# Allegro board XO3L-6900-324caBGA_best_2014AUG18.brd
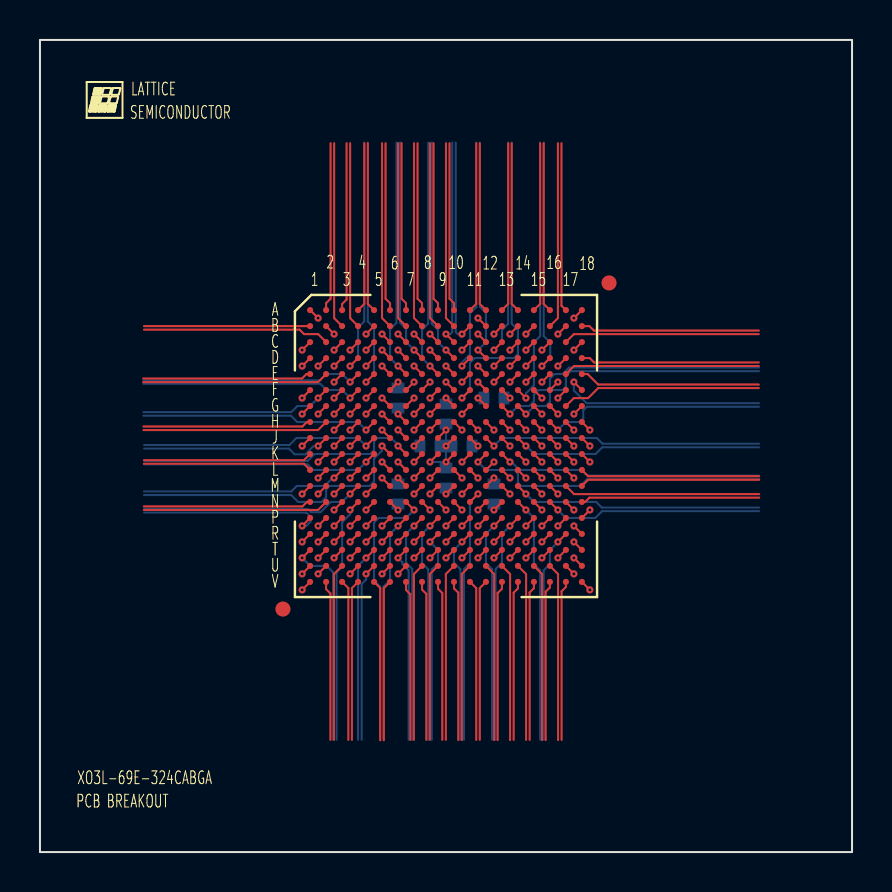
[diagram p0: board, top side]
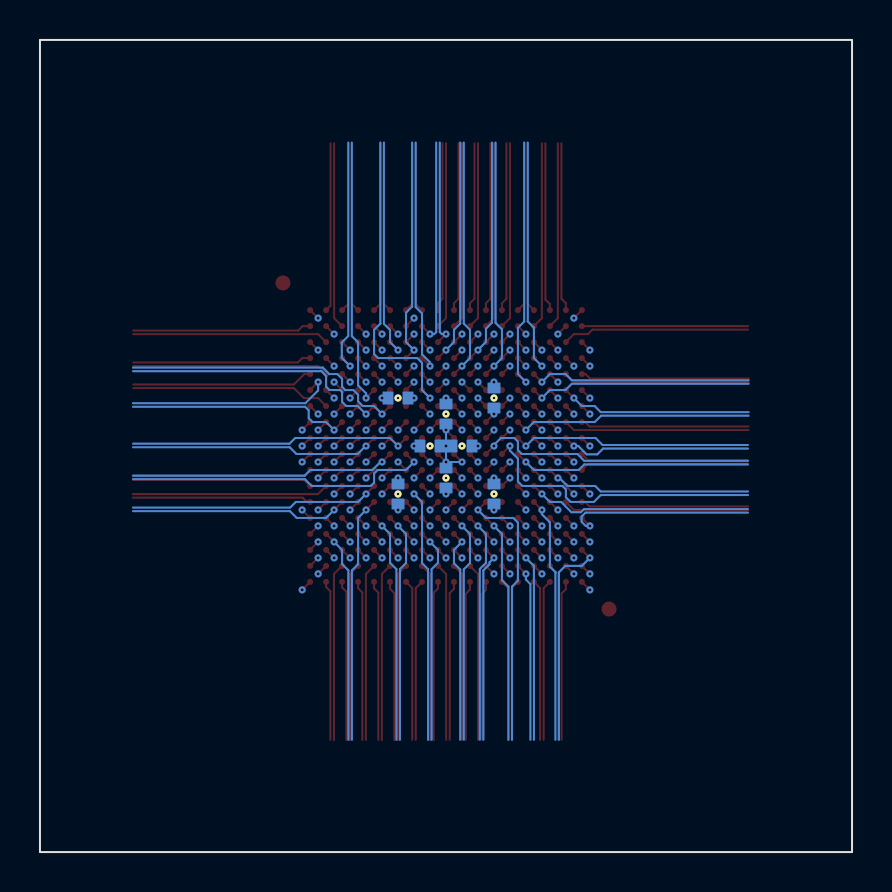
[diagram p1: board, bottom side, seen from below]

Outline 40.64 x 40.64 mm; copper layers: TOP, L2_GND, L3_SIGNAL, L4_SIGNAL, L5_PWR, BOTTOM. Coordinates in mm from the lower left corner of the outline.
Outline path: rectangle 0,0 40.64,40.64

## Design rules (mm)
net group CDPB4: nets PB4C PB4D
net group CDPB6: nets PB6C PB6D
net group CDPB7: nets PB7C PB7D
net group CDPB9: nets PB9C PB9D
net group CDPB13: nets PB13C PB13D
net group CDPB15: nets PB15C PB15D
net group CDPB16: nets PB16C PB16D
net group CDPB18: nets PB18C PB18D
net group CDPB21: nets PB21C PB21D
net group CDPB23: nets PB23C PB23D
net group CDPB26: nets PB26C PB26D
net group CDPB31: nets PB31C PB31D
net group CDPB35: nets PB35C PB35D
net group CDPB37: nets PB37C PB37D
net group CDPB38: nets PB38C PB38D
net group CDPL2: nets PL2C PL2D
net group CDPL3: nets PL3C PL3D
net group CDPL4: nets PL4C PL4D
net group CDPL5: nets PL5C PL5D
net group CDPL6: nets PL6C PL6D
net group CDPL7: nets PL7C PL7D
net group CDPL9: nets PL9C PL9D
net group CDPL10: nets PL10C PL10D
net group CDPL15: nets PL15C PL15D
net group CDPL16: nets PL16C PL16D
net group CDPL18: nets PL18C PL18D
net group CDPL19: nets PL19C PL19D
net group CDPL21: nets PL21C PL21D
net group CDPL23: nets PL23C PL23D
net group CDPL24: nets PL24C PL24D
net group CDPL25: nets PL25C PL25D
net group CDPR2: nets PR2C PR2D
net group CDPR3: nets PR3C PR3D
net group CDPR4: nets PR4C PR4D
net group CDPR6: nets PR6C PR6D
net group CDPR7: nets PR7C PR7D
net group CDPR8: nets PR8C PR8D
net group CDPR10: nets PR10C PR10D
net group CDPR11: nets PR11C PR11D
net group CDPR16: nets PR16C PR16D
net group CDPR17: nets PR17C PR17D
net group CDPR19: nets PR19C PR19D
net group CDPR21: nets PR21C PR21D
net group CDPR22: nets PR22C PR22D
net group CDPR23: nets PR23C PR23D
net group CDPR24: nets PR24C PR24D
net group CDPR25: nets PR25C PR25D
net group CDPT9: nets PT9C PT9D
net group CDPT10: nets PT10C PT10D
net group CDPT11: nets PT11C PT11D
net group CDPT14: nets PT14C PT14D
net group CDPT17: nets PT17C PT17D
net group CDPT18: nets PT18C PT18D
net group CDPT21: nets PT21C PT21D
net group CDPT22: nets PT22C PT22D
net group CDPT25: nets PT25C PT25D
net group CDPT26: nets PT26C PT26D
net group CDPT27: nets PT27C PT27D
net group CDPT33: nets PT33C PT33D
net group CDPT34: nets PT34C PT34D
net group CDPT35: nets PT35C PT35D
net group CDPT36: nets PT36C PT36D
net group PB4: nets PB4A PB4B
net group PB6: nets PB6A PB6B
net group PB7: nets PB7A PB7B
net group PB9: nets PB9A PB9B
net group PB10: nets PB10A PB10B
net group PB12: nets PB12A PB12B
net group PB13: nets PB13A PB13B
net group PB15: nets PB15A PB15B
net group PB16: nets PB16A PB16B
net group PB18: nets PB18A PB18B
net group PB21: nets PB21A PB21B
net group PB23: nets PB23A PB23B
net group PB26: nets PB26A PB26B
net group PB28: nets PB28A PB28B
net group PB29: nets PB29A PB29B
net group PB31: nets PB31A PB31B
net group PB32: nets PB32A PB32B
net group PB34: nets PB34A PB34B
net group PB35: nets PB35A PB35B
net group PB37: nets PB37A PB37B
net group PB38: nets PB38A PB38B
net group PL2: nets PL2A PL2B
net group PL3: nets PL3A PL3B
net group PL4: nets PL4A PL4B
net group PL5: nets PL5A PL5B
net group PL6: nets PL6A PL6B
net group PL8: nets PL8A PL8B
net group PL9: nets PL9A PL9B
net group PL10: nets PL10A PL10B
net group PL11: nets PL11A PL11B
net group PL12: nets PL12A PL12B
net group PL15: nets PL15A PL15B
net group PL17: nets PL17A PL17B
net group PL18: nets PL18A PL18B
net group PL19: nets PL19A PL19B
net group PL22: nets PL22A PL22B
net group PL23: nets PL23A PL23B
net group PL24: nets PL24A PL24B
net group PL25: nets PL25A PL25B
net group PR2: nets PR2A PR2B
net group PR3: nets PR3A PR3B
net group PR4: nets PR4A PR4B
net group PR5: nets PR5A PR5B
net group PR7: nets PR7A PR7B
net group PR8: nets PR8A PR8B
net group PR9: nets PR9A PR9B
net group PR11: nets PR11A PR11B
net group PR12: nets PR12A PR12B
net group PR15: nets PR15A PR15B
net group PR16: nets PR16A PR16B
net group PR17: nets PR17A PR17B
net group PR18: nets PR18A PR18B
net group PR21: nets PR21A PR21B
net group PR22: nets PR22A PR22B
net group PR23: nets PR23A PR23B
net group PR24: nets PR24A PR24B
net group PR25: nets PR25A PR25B
net group PT9: nets PT9A PT9B
net group PT10: nets PT10A PT10B
net group PT11: nets PT11A PT11B
net group PT12: nets PT12A PT12B
net group PT13: nets PT13A PT13B
net group PT14: nets PT14A PT14B
net group PT15: nets PT15A PT15B
net group PT16: nets PT16A PT16B
net group PT17: nets PT17A PT17B
net group PT18: nets PT18A PT18B
net group PT21: nets PT21A PT21B
net group PT22: nets PT22A PT22B
net group PT25: nets PT25A PT25B
net group PT26: nets PT26A PT26B
net group PT27: nets PT27A PT27B
net group PT28: nets PT28A PT28B
net group PT32: nets PT32A PT32B
net group PT33: nets PT33A PT33B
net group PT34: nets PT34A PT34B
net group PT35: nets PT35A PT35B
net group PT36: nets PT36A PT36B

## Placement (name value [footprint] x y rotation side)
BGA  -  [BGA324C80P18X18_1500X1500X17-1]  20.32 20.32 270 top
C1  VAL  [C0402]  17.92 22.72 90 bottom
C2  VAL  [C0402]  20.32 21.92 270 bottom
C3  VAL  [C0402]  22.72 17.92 270 bottom
C4  VAL  [C0402]  22.72 22.72 0 bottom
C5  VAL  [C0402]  19.52 20.32 0 bottom
C6  VAL  [C0402]  21.12 20.32 180 bottom
C7  VAL  [C0402]  20.32 18.72 90 bottom
C8  VAL  [C0402]  17.92 17.92 270 bottom
NOREF  -  []  24.69 13 0 top

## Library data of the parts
BGA = BGA324C80P18X18_1500X1500X17-1
C1-C8 = C0402: User Part Number: UPN; Tolerance: TOL

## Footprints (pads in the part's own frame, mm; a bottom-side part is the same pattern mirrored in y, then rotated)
BGA324C80P18X18_1500X1500X17-1
  round 0.75 smd: (-8.16,8.16) (8.16,-8.16)
  round 0.305 smd: A1(-6.8,-6.8) A2(-6.8,-6) A3(-6.8,-5.2) A4(-6.8,-4.4) A5(-6.8,-3.6) A6(-6.8,-2.8) A7(-6.8,-2) A8(-6.8,-1.2) A9(-6.8,-0.4) A10(-6.8,0.4) A11(-6.8,1.2) A12(-6.8,2) A13(-6.8,2.8) A14(-6.8,3.6) A15(-6.8,4.4) A16(-6.8,5.2) A17(-6.8,6) A18(-6.8,6.8) B1(-6,-6.8) B2(-6,-6) B3(-6,-5.2) B4(-6,-4.4) B5(-6,-3.6) B6(-6,-2.8) B7(-6,-2) B8(-6,-1.2) B9(-6,-0.4) B10(-6,0.4) B11(-6,1.2) B12(-6,2) B13(-6,2.8) B14(-6,3.6) B15(-6,4.4) B16(-6,5.2) B17(-6,6) B18(-6,6.8) C1(-5.2,-6.8) C2(-5.2,-6) C3(-5.2,-5.2) C4(-5.2,-4.4) C5(-5.2,-3.6) C6(-5.2,-2.8) C7(-5.2,-2) C8(-5.2,-1.2) C9(-5.2,-0.4) C10(-5.2,0.4) C11(-5.2,1.2) C12(-5.2,2) C13(-5.2,2.8) C14(-5.2,3.6) C15(-5.2,4.4) C16(-5.2,5.2) C17(-5.2,6) C18(-5.2,6.8) D1(-4.4,-6.8) D2(-4.4,-6) D3(-4.4,-5.2) D4(-4.4,-4.4) D5(-4.4,-3.6) D6(-4.4,-2.8) D7(-4.4,-2) D8(-4.4,-1.2) D9(-4.4,-0.4) D10(-4.4,0.4) D11(-4.4,1.2) D12(-4.4,2) D13(-4.4,2.8) D14(-4.4,3.6) D15(-4.4,4.4) D16(-4.4,5.2) D17(-4.4,6) D18(-4.4,6.8) E1(-3.6,-6.8) E2(-3.6,-6) E3(-3.6,-5.2) E4(-3.6,-4.4) E5(-3.6,-3.6) E6(-3.6,-2.8) E7(-3.6,-2) E8(-3.6,-1.2) E9(-3.6,-0.4) E10(-3.6,0.4) E11(-3.6,1.2) E12(-3.6,2) E13(-3.6,2.8) E14(-3.6,3.6) E15(-3.6,4.4) E16(-3.6,5.2) E17(-3.6,6) E18(-3.6,6.8) F1(-2.8,-6.8) F2(-2.8,-6) F3(-2.8,-5.2) F4(-2.8,-4.4) F5(-2.8,-3.6) F6(-2.8,-2.8) F7(-2.8,-2) F8(-2.8,-1.2) F9(-2.8,-0.4) F10(-2.8,0.4) F11(-2.8,1.2) F12(-2.8,2) F13(-2.8,2.8) F14(-2.8,3.6) F15(-2.8,4.4) F16(-2.8,5.2) F17(-2.8,6) F18(-2.8,6.8) G1(-2,-6.8) G2(-2,-6) G3(-2,-5.2) G4(-2,-4.4) G5(-2,-3.6) G6(-2,-2.8) G7(-2,-2) G8(-2,-1.2) G9(-2,-0.4) G10(-2,0.4) G11(-2,1.2) G12(-2,2) G13(-2,2.8) G14(-2,3.6) G15(-2,4.4) G16(-2,5.2) G17(-2,6) G18(-2,6.8) H1(-1.2,-6.8) H2(-1.2,-6) H3(-1.2,-5.2) H4(-1.2,-4.4) H5(-1.2,-3.6) H6(-1.2,-2.8) H7(-1.2,-2) H8(-1.2,-1.2) H9(-1.2,-0.4) H10(-1.2,0.4) H11(-1.2,1.2) H12(-1.2,2) H13(-1.2,2.8) H14(-1.2,3.6) H15(-1.2,4.4) H16(-1.2,5.2) H17(-1.2,6) H18(-1.2,6.8) J1(-0.4,-6.8) J2(-0.4,-6) J3(-0.4,-5.2) J4(-0.4,-4.4) J5(-0.4,-3.6) J6(-0.4,-2.8) J7(-0.4,-2) J8(-0.4,-1.2) J9(-0.4,-0.4) J10(-0.4,0.4) J11(-0.4,1.2) J12(-0.4,2) J13(-0.4,2.8) J14(-0.4,3.6) J15(-0.4,4.4) J16(-0.4,5.2) J17(-0.4,6) J18(-0.4,6.8) K1(0.4,-6.8) K2(0.4,-6) K3(0.4,-5.2) K4(0.4,-4.4) K5(0.4,-3.6) K6(0.4,-2.8) K7(0.4,-2) K8(0.4,-1.2) K9(0.4,-0.4) K10(0.4,0.4) K11(0.4,1.2) K12(0.4,2) K13(0.4,2.8) K14(0.4,3.6) K15(0.4,4.4) K16(0.4,5.2) K17(0.4,6) K18(0.4,6.8) L1(1.2,-6.8) L2(1.2,-6) L3(1.2,-5.2) L4(1.2,-4.4) L5(1.2,-3.6) L6(1.2,-2.8) L7(1.2,-2) L8(1.2,-1.2) L9(1.2,-0.4) L10(1.2,0.4) L11(1.2,1.2) L12(1.2,2) L13(1.2,2.8) L14(1.2,3.6) L15(1.2,4.4) L16(1.2,5.2) L17(1.2,6) L18(1.2,6.8) M1(2,-6.8) M2(2,-6) M3(2,-5.2) M4(2,-4.4) M5(2,-3.6) M6(2,-2.8) M7(2,-2) M8(2,-1.2) M9(2,-0.4) M10(2,0.4) M11(2,1.2) M12(2,2) M13(2,2.8) M14(2,3.6) M15(2,4.4) M16(2,5.2) M17(2,6) M18(2,6.8) N1(2.8,-6.8) N2(2.8,-6) N3(2.8,-5.2) N4(2.8,-4.4) N5(2.8,-3.6) N6(2.8,-2.8) N7(2.8,-2) N8(2.8,-1.2) N9(2.8,-0.4) N10(2.8,0.4) N11(2.8,1.2) N12(2.8,2) N13(2.8,2.8) N14(2.8,3.6) N15(2.8,4.4) N16(2.8,5.2) N17(2.8,6) N18(2.8,6.8) P1(3.6,-6.8) P2(3.6,-6) P3(3.6,-5.2) P4(3.6,-4.4) P5(3.6,-3.6) P6(3.6,-2.8) P7(3.6,-2) P8(3.6,-1.2) P9(3.6,-0.4) P10(3.6,0.4) P11(3.6,1.2) P12(3.6,2) P13(3.6,2.8) P14(3.6,3.6) P15(3.6,4.4) P16(3.6,5.2) P17(3.6,6) P18(3.6,6.8) R1(4.4,-6.8) R2(4.4,-6) R3(4.4,-5.2) R4(4.4,-4.4) R5(4.4,-3.6) R6(4.4,-2.8) R7(4.4,-2) R8(4.4,-1.2) R9(4.4,-0.4) R10(4.4,0.4) R11(4.4,1.2) R12(4.4,2) R13(4.4,2.8) R14(4.4,3.6) R15(4.4,4.4) R16(4.4,5.2) R17(4.4,6) R18(4.4,6.8) T1(5.2,-6.8) T2(5.2,-6) T3(5.2,-5.2) T4(5.2,-4.4) T5(5.2,-3.6) T6(5.2,-2.8) T7(5.2,-2) T8(5.2,-1.2) T9(5.2,-0.4) T10(5.2,0.4) T11(5.2,1.2) T12(5.2,2) T13(5.2,2.8) T14(5.2,3.6) T15(5.2,4.4) T16(5.2,5.2) T17(5.2,6) T18(5.2,6.8) U1(6,-6.8) U2(6,-6) U3(6,-5.2) U4(6,-4.4) U5(6,-3.6) U6(6,-2.8) U7(6,-2) U8(6,-1.2) U9(6,-0.4) U10(6,0.4) U11(6,1.2) U12(6,2) U13(6,2.8) U14(6,3.6) U15(6,4.4) U16(6,5.2) U17(6,6) U18(6,6.8) V1(6.8,-6.8) V2(6.8,-6) V3(6.8,-5.2) V4(6.8,-4.4) V5(6.8,-3.6) V6(6.8,-2.8) V7(6.8,-2) V8(6.8,-1.2) V9(6.8,-0.4) V10(6.8,0.4) V11(6.8,1.2) V12(6.8,2) V13(6.8,2.8) V14(6.8,3.6) V15(6.8,4.4) V16(6.8,5.2) V17(6.8,6) V18(6.8,6.8)
C0402
  rect 0.54x0.64 smd: 1(-0.5,0) 2(0.5,0)

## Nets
GND: BGA.A1 BGA.A18 BGA.B2 BGA.B17 BGA.F6 BGA.F13 BGA.J9 BGA.J10 BGA.K9 BGA.K10 BGA.N6 BGA.N13 BGA.U2 BGA.U17 BGA.V1 BGA.V18 C1.2 C2.2 C3.2 C4.2 C5.2 C6.2 C7.2 C8.2
VCC: BGA.G12 BGA.H8 BGA.H9 BGA.H10 BGA.H11 BGA.L8 BGA.L9 BGA.L10 BGA.L11 BGA.M12 C3.1 C4.1
VCCIO0: BGA.G8 BGA.G9 BGA.G10 BGA.G11 C2.1
VCCIO1: BGA.H12 BGA.J11 BGA.K11 BGA.L12 C6.1
VCCIO2: BGA.M8 BGA.M9 BGA.M10 BGA.M11 C7.1
VCCIO3: BGA.L7 BGA.M7 C8.1
VCCIO4: BGA.J8 BGA.K8 C5.1
VCCIO5: BGA.G7 BGA.H7 C1.1
PB4A: BGA.V2
PB4B: BGA.U3
PB4C: BGA.R4
PB4D: BGA.P6
PB6A: BGA.T3
PB6B: BGA.U4
PB6C: BGA.P5
PB6D: BGA.R6
PB7A: BGA.V3
PB7B: BGA.V4
PB7C: BGA.R5
PB7D: BGA.T4
PB9A: BGA.T5
PB9B: BGA.U5
PB9C: BGA.N7
PB9D: BGA.P7
PB10A: BGA.N8
PB10B: BGA.R7
PB12A: BGA.T6
PB12B: BGA.U6
PB13A: BGA.V5
PB13B: BGA.V6
PB13C: BGA.T7
PB13D: BGA.P8
PB15A: BGA.V7
PB15B: BGA.U8
PB15C: BGA.U7
PB15D: BGA.R8
PB16A: BGA.T8
PB16B: BGA.T9
PB16C: BGA.R9
PB16D: BGA.P9
PB18A: BGA.V8
PB18B: BGA.U9
PB18C: BGA.N9
PB18D: BGA.N10
PB21A: BGA.V9
PB21B: BGA.U10
PB21C: BGA.T10
PB21D: BGA.R10
PB23A: BGA.V10
PB23B: BGA.U11
PB23C: BGA.P10
PB23D: BGA.T11
PB26A: BGA.V11
PB26B: BGA.V12
PB26C: BGA.N11
PB26D: BGA.R11
PB28A: BGA.P11
PB28B: BGA.T12
PB29A: BGA.U12
PB29B: BGA.V13
PB31A: BGA.U13
PB31B: BGA.V14
PB31C: BGA.R12
PB31D: BGA.T13
PB32A: BGA.T14
PB32B: BGA.N12
PB34A: BGA.U14
PB34B: BGA.V15
PB35A: BGA.U15
PB35B: BGA.V16
PB35C: BGA.P12
PB35D: BGA.R14
PB37A: BGA.T15
PB37B: BGA.T16
PB37C: BGA.R13
PB37D: BGA.R15
PB38A: BGA.U16
PB38B: BGA.V17
PB38C: BGA.P13
PB38D: BGA.P14
PL2A: BGA.B1
PL2B: BGA.C2
PL2C: BGA.D3
PL2D: BGA.C1
PL3A: BGA.E4
PL3B: BGA.F4
PL3C: BGA.E3
PL3D: BGA.F5
PL4A: BGA.D2
PL4B: BGA.G5
PL4C: BGA.F3
PL4D: BGA.D1
PL5A: BGA.E2
PL5B: BGA.E1
PL5C: BGA.F2
PL5D: BGA.H5
PL6A: BGA.G4
PL6B: BGA.G3
PL6C: BGA.F1
PL6D: BGA.G6
PL7C: BGA.H3
PL7D: BGA.H4
PL8A: BGA.G2
PL8B: BGA.G1
PL9A: BGA.H2
PL9B: BGA.H1
PL9C: BGA.H6
PL9D: BGA.J1
PL10A: BGA.J2
PL10B: BGA.J5
PL10C: BGA.J3
PL10D: BGA.J7
PL11A: BGA.J4
PL11B: BGA.K3
PL12A: BGA.K2
PL12B: BGA.J6
PL15A: BGA.K1
PL15B: BGA.L1
PL15C: BGA.K7
PL15D: BGA.K5
PL16C: BGA.K6
PL16D: BGA.L3
PL17A: BGA.K4
PL17B: BGA.L2
PL18A: BGA.L4
PL18B: BGA.M2
PL18C: BGA.M1
PL18D: BGA.L6
PL19A: BGA.N1
PL19B: BGA.N2
PL19C: BGA.M3
PL19D: BGA.L5
PL21C: BGA.M5
PL21D: BGA.N3
PL22A: BGA.P1
PL22B: BGA.M4
PL23A: BGA.R1
PL23B: BGA.P3
PL23C: BGA.P2
PL23D: BGA.M6
PL24A: BGA.N4
PL24B: BGA.T1
PL24C: BGA.R2
PL24D: BGA.U1
PL25A: BGA.T2
PL25B: BGA.N5
PL25C: BGA.P4
PL25D: BGA.R3
PR2A: BGA.B18
PR2B: BGA.C17
PR2C: BGA.F14
PR2D: BGA.D16
PR3A: BGA.E15
PR3B: BGA.C18
PR3C: BGA.G13
PR3D: BGA.G14
PR4A: BGA.F15
PR4B: BGA.D17
PR4C: BGA.E16
PR4D: BGA.H13
PR5A: BGA.G15
PR5B: BGA.F16
PR6C: BGA.E17
PR6D: BGA.D18
PR7A: BGA.G16
PR7B: BGA.H15
PR7C: BGA.H14
PR7D: BGA.F17
PR8A: BGA.E18
PR8B: BGA.G17
PR8C: BGA.H16
PR8D: BGA.F18
PR9A: BGA.J15
PR9B: BGA.H17
PR10C: BGA.J13
PR10D: BGA.G18
PR11A: BGA.J16
PR11B: BGA.J17
PR11C: BGA.J14
PR11D: BGA.J12
PR12A: BGA.H18
PR12B: BGA.K15
PR15A: BGA.K14
PR15B: BGA.J18
PR16A: BGA.K16
PR16B: BGA.K17
PR16C: BGA.K12
PR16D: BGA.K13
PR17A: BGA.K18
PR17B: BGA.L16
PR17C: BGA.L15
PR17D: BGA.L13
PR18A: BGA.L17
PR18B: BGA.M16
PR19C: BGA.L18
PR19D: BGA.M18
PR21A: BGA.M17
PR21B: BGA.N18
PR21C: BGA.L14
PR21D: BGA.N17
PR22A: BGA.M15
PR22B: BGA.P18
PR22C: BGA.M14
PR22D: BGA.N16
PR23A: BGA.P17
PR23B: BGA.N15
PR23C: BGA.R18
PR23D: BGA.M13
PR24A: BGA.P16
PR24B: BGA.T18
PR24C: BGA.R17
PR24D: BGA.N14
PR25A: BGA.P15
PR25B: BGA.U18
PR25C: BGA.R16
PR25D: BGA.T17
PT9A: BGA.A2
PT9B: BGA.B3
PT9C: BGA.D4
PT9D: BGA.E5
PT10A: BGA.C3
PT10B: BGA.C4
PT10C: BGA.F7
PT10D: BGA.E6
PT11A: BGA.A3
PT11B: BGA.B4
PT11C: BGA.D5
PT11D: BGA.B5
PT12A: BGA.A4
PT12B: BGA.A5
PT13A: BGA.C5
PT13B: BGA.D6
PT14A: BGA.B6
PT14B: BGA.A6
PT14C: BGA.D7
PT14D: BGA.C6
PT15A: BGA.A7
PT15B: BGA.B7
PT16A: BGA.D8
PT16B: BGA.E7
PT17A: BGA.B8
PT17B: BGA.A8
PT17C: BGA.C7
PT17D: BGA.C8
PT18A: BGA.A9
PT18B: BGA.B9
PT18C: BGA.E8
PT18D: BGA.F8
PT21A: BGA.A10
PT21B: BGA.B10
PT21C: BGA.C9
PT21D: BGA.D9
PT22A: BGA.C10
PT22B: BGA.B11
PT22C: BGA.E9
PT22D: BGA.D10
PT25A: BGA.B12
PT25B: BGA.C11
PT25C: BGA.F9
PT25D: BGA.F10
PT26A: BGA.A11
PT26B: BGA.A12
PT26C: BGA.E10
PT26D: BGA.E11
PT27A: BGA.C12
PT27B: BGA.B13
PT27C: BGA.D11
PT27D: BGA.D12
PT28A: BGA.A13
PT28B: BGA.A14
PT32A: BGA.F11
PT32B: BGA.C13
PT33A: BGA.B14
PT33B: BGA.B15
PT33C: BGA.E12
PT33D: BGA.F12
PT34A: BGA.C14
PT34B: BGA.C15
PT34C: BGA.D13
PT34D: BGA.E13
PT35A: BGA.A15
PT35B: BGA.A16
PT35C: BGA.D14
PT35D: BGA.D15
PT36A: BGA.B16
PT36B: BGA.A17
PT36C: BGA.C16
PT36D: BGA.E14

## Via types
v1: diameter 0.356, hole 0.152, TOP to BOTTOM, 254 vias

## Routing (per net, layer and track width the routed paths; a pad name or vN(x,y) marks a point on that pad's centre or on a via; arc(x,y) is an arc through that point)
GND: length 13.9
  TOP w0.102: BGA.J10 v1(20.32,20.32) ; BGA.K9 v1(19.52,19.52) ; BGA.K10 v1(20.32,19.52) ; BGA.U17 v1(26.72,13.92) ; BGA.B2 v1(14.72,25.92) ; BGA.B17 v1(25.92,25.92) ; BGA.F6 v1(17.92,23.52) ; BGA.U2 v1(13.92,13.92) ; BGA.N13 v1(22.72,17.12) ; BGA.A1 v1(13.92,26.72) ; BGA.F13 v1(23.52,22.72) ; BGA.A18 v1(26.72,26.72) ; BGA.V1 v1(13.12,13.12) ; BGA.V18 v1(27.52,13.12) ; BGA.J9 v1(20.32,21.12) ; BGA.N6 v1(17.92,17.12)
  BOTTOM w0.102: v1(20.32,20.32) v1(20.32,21.12) C2.2 ; v1(20.32,20.32) C5.2 ; v1(20.32,20.32) v1(20.32,19.52) ; v1(20.32,20.32) C6.2 ; C4.2 v1(23.52,22.72) ; C1.2 v1(17.92,23.52) ; v1(20.32,19.52) v1(19.52,19.52) ; v1(20.32,19.52) C7.2 ; C3.2 v1(22.72,17.12) ; C8.2 v1(17.92,17.12)
VCC: length 6.3
  TOP w0.102: BGA.H9 v1(19.52,21.12) ; BGA.H8 v1(18.72,21.12) ; BGA.H11 v1(21.92,21.12) ; BGA.L11 v1(21.92,18.72) ; BGA.M12 v1(22.72,18.72) ; BGA.L10 v1(21.12,18.72) ; BGA.G12 v1(21.92,22.72) ; BGA.L8 v1(18.72,18.72) ; BGA.H10 v1(21.12,21.12) ; BGA.L9 v1(19.52,18.72)
  BOTTOM w0.102: C3.1 v1(22.72,18.72) ; C4.1 v1(21.92,22.72)
VCCIO0: length 2.6
  TOP w0.102: BGA.G8 v1(18.72,21.92) ; BGA.G9 v1(19.52,21.92) ; BGA.G11 v1(21.12,21.92) ; BGA.G10 v1(20.32,22.72)
  BOTTOM w0.102: C2.1 v1(20.32,22.72)
VCCIO1: length 2.6
  TOP w0.102: BGA.K11 v1(21.12,19.52) ; BGA.J11 v1(21.92,20.32) ; BGA.H12 v1(22.72,21.12) ; BGA.L12 v1(22.72,19.52)
  BOTTOM w0.102: C6.1 v1(21.92,20.32)
VCCIO2: length 2.6
  TOP w0.102: BGA.M11 v1(21.12,17.92) ; BGA.M9 v1(19.52,17.92) ; BGA.M10 v1(20.32,17.92) ; BGA.M8 v1(18.72,17.92)
  BOTTOM w0.102: C7.1 v1(20.32,17.92)
VCCIO3: length 1.4
  TOP w0.102: BGA.M7 v1(17.92,18.72) ; BGA.L7 v1(17.92,19.52)
  BOTTOM w0.102: C8.1 v1(17.92,18.72)
VCCIO4: length 1.4
  TOP w0.102: BGA.J8 v1(18.72,20.32) ; BGA.K8 v1(18.72,19.52)
  BOTTOM w0.102: C5.1 v1(18.72,20.32)
VCCIO5: length 1.4
  TOP w0.102: BGA.G7 v1(18.72,22.72) ; BGA.H7 v1(17.92,21.92)
  BOTTOM w0.102: C1.1 v1(17.92,21.92)
PB4A: length 8
  TOP w0.102: BGA.V2 14.32,13.15 14.53,12.94 14.53,5.62
PB4B: length 8.9
  TOP w0.102: BGA.U3 14.71,13.91 14.71,5.62
PB4C: length 10.8
  TOP w0.102: BGA.R4 v1(15.52,15.52)
  L3_SIGNAL w0.102: v1(15.52,15.52) 15.92,15.12 15.92,13.75 16.23,13.44 16.23,5.63
PB4D: length 11.6
  TOP w0.102: BGA.P6 v1(17.12,16.32)
  L3_SIGNAL w0.102: 16.41,5.63 16.41,13.44 16.72,13.75 16.72,15.69 17.12,16.09 v1(17.12,16.32)
PB6A: length 9.9
  TOP w0.102: BGA.T3 v1(14.72,14.72)
  L3_SIGNAL w0.102: v1(14.72,14.72) 14.99,14.45 14.99,14.31 14.6,13.92 14.6,5.63
PB6B: length 9.8
  TOP w0.102: BGA.U4 v1(15.52,13.92)
  L3_SIGNAL w0.102: 14.78,5.63 14.78,13.85 15.11,14.19 15.25,14.19 v1(15.52,13.92)
PB6C: length 11.6
  TOP w0.102: BGA.P5 v1(16.32,16.32)
  L4_SIGNAL w0.102: 17.04,5.61 17.04,13.28 16.72,13.6 16.72,15.92 v1(16.32,16.32)
PB6D: length 10.8
  TOP w0.102: BGA.R6 v1(17.12,15.52)
  L4_SIGNAL w0.102: v1(17.12,15.52) 17.52,15.12 17.52,13.59 17.21,13.29 17.21,5.61
PB7A: length 8
  TOP w0.102: BGA.V3 15.43,13.21 15.43,5.62
PB7B: length 8
  TOP w0.102: 15.61,5.62 15.61,13.21 BGA.V4
PB7C: length 10.8
  TOP w0.102: BGA.R5 v1(16.32,15.52)
  L4_SIGNAL w0.102: 15.61,5.61 15.61,13.34 15.92,13.65 15.92,15.12 v1(16.32,15.52)
PB7D: length 10
  TOP w0.102: BGA.T4 v1(15.52,14.72)
  L4_SIGNAL w0.102: v1(15.52,14.72) 15.09,14.29 15.09,13.69 15.44,13.35 15.44,5.61
PB9A: length 9.8
  TOP w0.102: BGA.T5 v1(16.32,14.72)
  BOTTOM w0.102: 15.92,5.62 15.92,14.32 v1(16.32,14.72)
PB9B: length 9
  TOP w0.102: BGA.U5 v1(16.32,13.92)
  BOTTOM w0.102: 16.1,5.62 16.1,13.41 16.32,13.63 v1(16.32,13.92)
PB9C: length 13.8
  TOP w0.102: BGA.N7 v1(18.72,17.12)
  BOTTOM w0.102: 17.02,5.62 17.02,13.28 16.72,13.58 16.72,16.49 16.95,16.72 18.32,16.72 v1(18.72,17.12)
PB9D: length 11.6
  TOP w0.102: BGA.P7 v1(17.92,16.32)
  BOTTOM w0.102: 17.19,5.62 17.19,13.28 17.52,13.61 17.52,14.09 17.52,15.92 v1(17.92,16.32)
PB10A: length 12.4
  TOP w0.102: BGA.N8 v1(19.52,17.12)
  L4_SIGNAL w0.102: v1(19.52,17.12) 19.12,16.72 19.12,14.31 18.83,14.02 18.83,5.61
PB10B: length 10.8
  TOP w0.102: BGA.R7 v1(17.92,15.52)
  L4_SIGNAL w0.102: 18.65,5.61 18.65,14.01 18.32,14.34 18.32,15.12 v1(17.92,15.52)
PB12A: length 9.8
  TOP w0.102: BGA.T6 v1(17.12,14.72)
  L3_SIGNAL w0.102: v1(17.12,14.72) 17.52,14.32 17.52,5.63
PB12B: length 9
  TOP w0.102: v1(17.12,13.92) BGA.U6
  L3_SIGNAL w0.102: 17.34,5.63 17.34,13.37 17.12,13.59 v1(17.12,13.92)
PB13A: length 8.1
  TOP w0.102: 17.03,5.59 17.03,13.21 BGA.V5
PB13B: length 8.1
  TOP w0.102: 17.21,5.59 17.21,13.21 BGA.V6
PB13C: length 9.9
  TOP w0.102: BGA.T7 v1(17.92,14.72)
  BOTTOM w0.102: 18.45,5.62 18.45,14.09 18.14,14.4 18.14,14.5 v1(17.92,14.72)
PB13D: length 11.6
  TOP w0.102: BGA.P8 v1(18.72,16.32)
  BOTTOM w0.102: v1(18.72,16.32) 18.32,15.92 18.32,14.48 18.63,14.17 18.63,5.62
PB15A: length 8
  TOP w0.102: BGA.V7 18.32,13.11 18.53,12.9 18.53,5.62
PB15B: length 8.9
  TOP w0.102: 18.71,5.62 18.71,13.91 BGA.U8
PB15C: length 9
  TOP w0.102: v1(17.92,13.92) BGA.U7
  L3_SIGNAL w0.102: 18.14,5.63 18.14,13.39 17.92,13.61 v1(17.92,13.92)
PB15D: length 10.6
  TOP w0.102: BGA.R8 v1(18.72,15.52)
  L3_SIGNAL w0.102: v1(18.72,15.52) 18.69,15.52 18.32,15.15 18.32,5.63
PB16A: length 9.9
  TOP w0.102: BGA.T8 v1(18.72,14.72)
  L3_SIGNAL w0.102: 19.03,5.63 19.03,14.62 18.93,14.72 v1(18.72,14.72)
PB16B: length 9.9
  TOP w0.102: BGA.T9 v1(19.52,14.72)
  L3_SIGNAL w0.102: 19.21,5.63 19.21,14.62 19.31,14.72 v1(19.52,14.72)
PB16C: length 10.8
  TOP w0.102: BGA.R9 v1(19.52,15.52)
  BOTTOM w0.102: v1(19.52,15.52) 19.92,15.12 19.92,14.45 19.61,14.14 19.61,5.62
PB16D: length 11.6
  TOP w0.102: BGA.P9 v1(19.52,16.32)
  BOTTOM w0.102: v1(19.52,16.32) 19.12,15.92 19.12,14.46 19.43,14.15 19.43,5.62
PB18A: length 8
  TOP w0.102: 19.33,5.62 19.33,12.92 19.12,13.13 BGA.V8
PB18B: length 8.9
  TOP w0.102: 19.51,5.62 19.51,13.91 BGA.U9
PB18C: length 12.4
  TOP w0.102: BGA.N9 v1(20.32,17.12)
  L4_SIGNAL w0.102: 20.23,5.61 20.23,14.17 19.92,14.47 19.92,16.72 v1(20.32,17.12)
PB18D: length 12.4
  TOP w0.102: BGA.N10 v1(21.12,17.12)
  L4_SIGNAL w0.102: 20.41,5.61 20.41,14.16 20.72,14.47 20.72,16.72 v1(21.12,17.12)
PB21A: length 8
  TOP w0.102: BGA.V9 19.92,13.17 20.13,12.96 20.13,5.62
PB21B: length 8.9
  TOP w0.102: BGA.U10 20.31,13.91 20.31,5.62
PB21C: length 9.8
  TOP w0.102: BGA.T10 v1(20.32,14.72)
  L3_SIGNAL w0.102: 20.1,5.63 20.1,14.17 20.32,14.4 v1(20.32,14.72)
PB21D: length 10.6
  TOP w0.102: BGA.R10 v1(20.32,15.52)
  L3_SIGNAL w0.102: v1(20.32,15.52) 19.92,15.12 19.92,5.63
PB23A: length 8
  TOP w0.102: BGA.V10 20.72,13.19 20.93,12.98 20.93,5.6
PB23B: length 8.9
  TOP w0.102: 21.11,5.6 21.11,13.91 BGA.U11
PB23C: length 11.4
  TOP w0.102: BGA.P10 v1(20.32,16.32)
  L3_SIGNAL w0.102: 20.72,5.63 20.72,15.92 v1(20.32,16.32)
PB23D: length 9.8
  TOP w0.102: BGA.T11 v1(21.12,14.72)
  L3_SIGNAL w0.102: v1(21.12,14.72) 21.12,14.4 20.9,14.18 20.9,5.63
PB26A: length 8
  TOP w0.102: 21.83,5.62 21.83,13.21 BGA.V11
PB26B: length 8
  TOP w0.102: 22.01,5.62 22.01,13.21 BGA.V12
PB26C: length 13.2
  TOP w0.102: BGA.N11 v1(21.92,17.92)
  BOTTOM w0.102: v1(21.92,17.92) BGA.N11 21.52,14.46 21.22,14.16 21.22,5.62
PB26D: length 10.8
  TOP w0.102: BGA.R11 v1(21.12,15.52)
  BOTTOM w0.102: 21.04,5.62 21.04,14.15 20.72,14.47 20.72,15.12 v1(21.12,15.52)
PB28A: length 11.4
  TOP w0.102: BGA.P11 v1(21.12,16.32)
  L3_SIGNAL w0.102: 21.52,5.63 21.52,5.73 21.52,15.92 v1(21.12,16.32)
PB28B: length 9.7
  TOP w0.102: BGA.T12 v1(21.92,14.72)
  L3_SIGNAL w0.102: 21.7,5.63 21.7,5.73 21.7,14.18 21.92,14.4 v1(21.92,14.72)
PB29A: length 8.9
  TOP w0.102: 22.73,5.6 22.73,13.91 BGA.U12
PB29B: length 8
  TOP w0.102: 22.91,5.6 22.91,12.96 23.12,13.17 BGA.V13
PB31A: length 8.9
  TOP w0.102: BGA.U13 23.53,13.91 23.53,5.6
PB31B: length 8
  TOP w0.102: 23.71,5.62 23.71,12.98 23.92,13.19 BGA.V14
PB31C: length 10.6
  TOP w0.102: BGA.R12 v1(21.92,15.52)
  L3_SIGNAL w0.102: 22.32,5.61 22.32,15.12 v1(21.92,15.52)
PB31D: length 9.8
  TOP w0.102: BGA.T13 v1(22.72,14.72)
  L3_SIGNAL w0.102: 22.5,5.61 22.5,14.18 22.72,14.4 v1(22.72,14.72)
PB32A: length 9.8
  TOP w0.102: BGA.T14 v1(23.52,14.72)
  L3_SIGNAL w0.102: 23.3,5.61 23.3,14.18 23.52,14.4 v1(23.52,14.72)
PB32B: length 12.9
  TOP w0.102: BGA.N12 v1(21.92,17.12)
  L3_SIGNAL w0.102: 23.12,5.61 23.12,14.55 23.12,15.35 23.12,16.15 23.12,16.49 22.89,16.72 22.32,16.72 v1(21.92,17.12)
PB34A: length 8.9
  TOP w0.102: 24.33,5.62 24.33,13.91 BGA.U14
PB34B: length 8
  TOP w0.102: BGA.V15 24.72,13.2 24.51,12.99 24.51,5.62
PB35A: length 8.9
  TOP w0.102: BGA.U15 25.13,13.91 25.13,5.6
PB35B: length 8
  TOP w0.102: 25.31,5.6 25.31,13.03 25.52,13.24 BGA.V16
PB35C: length 11.6
  TOP w0.102: BGA.P12 v1(21.92,16.32)
  L4_SIGNAL w0.102: v1(21.92,16.32) 21.52,15.92 21.52,14.48 21.83,14.17 21.83,5.61
PB35D: length 12.2
  TOP w0.102: BGA.R14 v1(23.52,15.52)
  L4_SIGNAL w0.102: v1(23.52,15.52) 23.12,15.92 22.55,15.92 22.32,15.69 22.32,14.48 22.01,14.17 22.01,5.61
PB37A: length 9.9
  TOP w0.102: BGA.T15 v1(24.32,14.72)
  L3_SIGNAL w0.102: 24.63,5.62 24.63,14.62 24.53,14.72 v1(24.32,14.72)
PB37B: length 9.9
  TOP w0.102: BGA.T16 v1(25.12,14.72)
  L3_SIGNAL w0.102: v1(25.12,14.72) 24.91,14.72 24.81,14.62 24.81,5.62
PB37C: length 10.8
  TOP w0.102: BGA.R13 v1(22.72,15.52)
  L4_SIGNAL w0.102: v1(22.72,15.52) 23.12,15.12 23.12,14.44 23.46,14.1 23.46,5.61
PB37D: length 10.8
  TOP w0.102: BGA.R15 v1(24.32,15.52)
  L4_SIGNAL w0.102: 23.64,5.61 23.64,14.11 23.92,14.39 23.92,15.12 v1(24.32,15.52)
PB38A: length 8.9
  TOP w0.102: 25.93,5.6 25.93,13.91 BGA.U16
PB38B: length 8
  TOP w0.102: BGA.V17 26.32,13.26 26.11,13.05 26.11,5.62
PB38C: length 11.6
  TOP w0.102: BGA.P13 v1(22.72,16.32)
  BOTTOM w0.102: v1(22.72,16.32) 22.32,15.92 22.32,14.46 22.62,14.16 22.62,5.62
PB38D: length 11.6
  TOP w0.102: BGA.P14 v1(23.52,16.32)
  BOTTOM w0.102: v1(23.52,16.32) 23.12,15.92 23.12,14.48 22.8,14.16 22.8,5.62
PL2A: length 8.3
  TOP w0.102: BGA.B1 5.21,26.32
PL2B: length 9.4
  TOP w0.102: BGA.C2 13.92,25.92 13.22,25.92 12.99,26.14 5.21,26.14
PL2C: length 10.2
  TOP w0.102: BGA.D3 v1(14.72,24.32)
  L3_SIGNAL w0.102: 5.21,24.72 14.32,24.72 v1(14.72,24.32)
PL2D: length 8.6
  TOP w0.102: BGA.C1 v1(13.12,25.12)
  L3_SIGNAL w0.102: v1(13.12,25.12) 12.76,25.12 12.54,24.9 5.21,24.9
PL3A: length 11.2
  TOP w0.102: BGA.E4 v1(15.52,23.52)
  BOTTOM w0.102: 5.18,23.61 14.03,23.61 14.34,23.92 15.12,23.92 v1(15.52,23.52)
PL3B: length 11.2
  TOP w0.102: BGA.F4 v1(15.52,22.72)
  BOTTOM w0.102: v1(15.52,22.72) 15.12,23.12 14.34,23.12 14.03,23.43 5.18,23.43
PL3C: length 10.2
  TOP w0.102: BGA.E3 v1(14.72,23.52)
  L3_SIGNAL w0.102: 5.21,23.3 14.15,23.3 14.38,23.52 v1(14.72,23.52)
PL3D: length 11.8
  TOP w0.102: BGA.F5 v1(16.32,22.72)
  L3_SIGNAL w0.102: 5.21,23.12 15.92,23.12 v1(16.32,22.72)
PL4A: length 12
  TOP w0.102: BGA.D2 v1(13.92,24.32)
  L4_SIGNAL w0.102: v1(13.92,24.32) 14.3,24.7 14.3,26.22 14.62,26.54 14.62,35.44
PL4B: length 14.9
  TOP w0.102: BGA.G5 v1(16.32,21.92)
  L4_SIGNAL w0.102: v1(16.32,21.92) 15.92,22.32 15.92,22.89 15.69,23.12 15.35,23.12 15.12,23.35 15.12,23.38 15.12,26.21 14.8,26.54 14.8,35.44
PL4C: length 10.5
  TOP w0.102: BGA.F3 v1(14.72,22.72)
  L4_SIGNAL w0.102: 5.16,23.22 13.75,23.22 13.91,23.39 14.05,23.39 v1(14.72,22.72)
PL4D: length 10.3
  TOP w0.102: BGA.D1 v1(13.12,24.32)
  L4_SIGNAL w0.102: 5.16,23.4 13.67,23.4 13.79,23.51 13.79,23.65 v1(13.12,24.32)
PL5A: length 9.3
  TOP w0.102: 5.17,23.52 13.92,23.52 BGA.E2
PL5B: length 8.4
  TOP w0.102: 5.17,23.7 13.11,23.7 13.34,23.92 BGA.E1
PL5C: length 9.6
  TOP w0.102: BGA.F2 v1(13.92,22.72)
  BOTTOM w0.102: v1(13.92,22.72) 13.52,22.32 12.88,22.32 12.58,22.01 5.18,22.01
PL5D: length 12
  TOP w0.102: BGA.H5 v1(16.32,21.12)
  BOTTOM w0.102: v1(16.32,21.12) 15.92,21.52 15.69,21.52 15.69,21.52 15.35,21.52 15.35,21.52 14.89,21.52 14.89,21.52 14.55,21.52 14.55,21.52 12.87,21.52 12.56,21.84 5.18,21.84
PL6A: length 11.2
  TOP w0.102: BGA.G4 v1(15.52,21.92)
  L4_SIGNAL w0.102: 5.16,21.29 14.22,21.29 14.44,21.52 15.12,21.52 v1(15.52,21.92)
PL6B: length 10.3
  TOP w0.102: BGA.G3 v1(14.72,21.92)
  L4_SIGNAL w0.102: 5.16,21.47 14.14,21.47 14.37,21.7 14.5,21.7 v1(14.72,21.92)
PL6C: length 8.6
  TOP w0.102: BGA.F1 v1(13.12,22.72)
  L3_SIGNAL w0.102: 5.21,22.5 12.51,22.5 12.73,22.72 v1(13.12,22.72)
PL6D: length 12.6
  TOP w0.102: BGA.G6 v1(17.12,22.72)
  L3_SIGNAL w0.102: v1(17.12,22.72) 17.12,22.71 16.73,22.32 5.21,22.32
PL7C: length 10.1
  TOP w0.102: BGA.H3 v1(14.72,21.12)
  L3_SIGNAL w0.102: 5.21,21.02 14.11,21.02 14.21,21.12 v1(14.72,21.12)
PL7D: length 11.2
  TOP w0.102: BGA.H4 v1(15.52,21.12)
  L3_SIGNAL w0.102: 5.21,21.2 14.04,21.2 14.36,21.52 15.12,21.52 v1(15.52,21.12)
PL8A: length 9.4
  TOP w0.102: BGA.G2 v1(13.92,21.92)
  L3_SIGNAL w0.102: 5.21,21.51 13.51,21.51 13.92,21.92 v1(13.92,21.92)
PL8B: length 8.6
  TOP w0.102: BGA.G1 v1(13.12,21.92)
  L3_SIGNAL w0.102: 5.21,21.68 12.55,21.68 12.79,21.92 v1(13.12,21.92)
PL9A: length 9.3
  TOP w0.102: 5.18,21.12 13.92,21.12 BGA.H2
PL9B: length 8.4
  TOP w0.102: 5.18,21.3 13.13,21.3 13.36,21.52 BGA.H1
PL9C: length 13.3
  TOP w0.102: BGA.H6 v1(17.12,21.92)
  L3_SIGNAL w0.102: 5.21,20.72 12.98,20.72 16.54,20.72 16.72,20.9 16.72,21.52 v1(17.12,21.92)
PL9D: length 8.6
  TOP w0.102: BGA.J1 v1(13.12,20.32)
  L3_SIGNAL w0.102: 5.21,20.54 12.53,20.54 12.75,20.32 v1(13.12,20.32)
PL10A: length 9.6
  TOP w0.102: BGA.J2 v1(13.92,20.32)
  BOTTOM w0.102: v1(13.92,20.32) 13.7,20.32 13.28,19.9 12.75,19.9 12.46,20.19 5.21,20.19
PL10B: length 12
  TOP w0.102: BGA.J5 v1(16.32,20.32)
  BOTTOM w0.102: v1(16.32,20.32) 16.32,20.32 15.92,20.72 12.84,20.72 12.49,20.37 5.21,20.37
PL10C: length 10.3
  TOP w0.102: BGA.J3 v1(14.72,20.32)
  L4_SIGNAL w0.102: v1(14.72,20.32) 14.5,20.54 14.4,20.54 14.18,20.77 5.16,20.77
PL10D: length 13.6
  TOP w0.102: BGA.J7 v1(17.92,21.12)
  L4_SIGNAL w0.102: 5.16,20.94 14.25,20.94 14.47,20.72 17.52,20.72 v1(17.92,21.12)
PL11A: length 11.2
  TOP w0.102: BGA.J4 v1(15.52,20.32)
  L4_SIGNAL w0.102: 5.16,19.61 13.25,19.61 13.56,19.92 15.12,19.92 v1(15.52,20.32)
PL11B: length 10.4
  TOP w0.102: BGA.K3 v1(14.72,19.52)
  L4_SIGNAL w0.102: 5.16,19.43 13.24,19.43 13.55,19.12 14.32,19.12 v1(14.72,19.52)
PL12A: length 9.4
  TOP w0.102: BGA.K2 v1(13.92,19.52)
  L3_SIGNAL w0.102: v1(13.92,19.52) 13.53,19.52 13.31,19.74 5.21,19.74
PL12B: length 13.3
  TOP w0.102: BGA.J6 v1(17.12,21.12)
  L3_SIGNAL w0.102: 5.21,19.92 16.54,19.92 16.72,20.1 16.72,20.49 17.12,20.89 v1(17.12,21.12)
PL15A: length 8.4
  TOP w0.102: BGA.K1 13.21,19.61 5.2,19.61
PL15B: length 8.4
  TOP w0.102: 5.2,19.43 13.21,19.43 BGA.L1
PL15C: length 14.2
  TOP w0.102: BGA.K7 v1(17.92,20.32)
  BOTTOM w0.102: v1(17.92,20.32) 17.92,20.37 17.57,20.72 16.9,20.72 16.72,20.54 16.72,20.11 16.53,19.92 13.74,19.92 13.4,19.58 5.21,19.58
PL15D: length 12
  TOP w0.102: BGA.K5 v1(16.32,19.52)
  BOTTOM w0.102: v1(16.32,19.52) 15.92,19.12 13.68,19.12 13.4,19.4 5.21,19.4
PL16C: length 14.8
  TOP w0.102: BGA.K6 v1(17.12,20.32)
  BOTTOM w0.102: 5.21,17.87 12.58,17.87 12.92,17.52 14.09,17.52 14.32,17.75 14.32,18.15 14.49,18.32 16.5,18.32 16.72,18.54 16.72,19.69 16.72,19.69 17.12,20.09 v1(17.12,20.32)
PL16D: length 10.4
  TOP w0.102: BGA.L3 v1(14.72,18.72)
  BOTTOM w0.102: v1(14.72,18.72) 14.64,18.72 14.24,18.32 12.85,18.32 12.58,18.04 5.21,18.04
PL17A: length 11
  TOP w0.102: BGA.K4 v1(15.52,19.52)
  L3_SIGNAL w0.102: v1(15.52,19.52) 15.12,19.12 5.21,19.12
PL17B: length 9.4
  TOP w0.102: BGA.L2 v1(13.92,18.72)
  L3_SIGNAL w0.102: v1(13.92,18.72) 13.65,18.72 13.42,18.94 5.21,18.94
PL18A: length 11.2
  TOP w0.102: BGA.L4 v1(15.52,18.72)
  L4_SIGNAL w0.102: v1(15.52,18.72) 15.12,18.32 13.64,18.32 13.36,18.6 5.16,18.6
PL18B: length 9.5
  TOP w0.102: BGA.M2 v1(13.92,17.92)
  L4_SIGNAL w0.102: 5.16,18.43 13.28,18.43 13.79,17.92 v1(13.92,17.92)
PL18C: length 8.6
  TOP w0.102: BGA.M1 v1(13.12,17.92)
  L3_SIGNAL w0.102: 5.21,18.14 12.57,18.14 12.79,17.92 v1(13.12,17.92)
PL18D: length 13.3
  TOP w0.102: BGA.L6 v1(17.12,19.52)
  L3_SIGNAL w0.102: 5.21,18.32 16.49,18.32 16.72,18.55 16.72,19.12 v1(17.12,19.52)
PL19A: length 8.4
  TOP w0.102: BGA.N1 13.36,17.52 13.13,17.3 5.2,17.3
PL19B: length 9.3
  TOP w0.102: BGA.N2 13.92,17.12 5.2,17.12
PL19C: length 10.3
  TOP w0.102: BGA.M3 v1(14.72,17.92)
  L4_SIGNAL w0.102: 5.16,17.43 14.08,17.43 14.57,17.92 v1(14.72,17.92)
PL19D: length 12.7
  TOP w0.102: BGA.L5 v1(16.32,18.72)
  L4_SIGNAL w0.102: v1(16.32,18.72) 15.92,18.32 15.92,17.69 15.75,17.52 14.42,17.52 14.15,17.25 5.16,17.25
PL21C: length 11.8
  TOP w0.102: BGA.M5 v1(16.32,17.92)
  L3_SIGNAL w0.102: 5.21,17.52 15.92,17.52 v1(16.32,17.92)
PL21D: length 10.2
  TOP w0.102: BGA.N3 v1(14.72,17.12)
  L3_SIGNAL w0.102: 5.21,17.34 14.14,17.34 14.36,17.12 v1(14.72,17.12)
PL22A: length 9.7
  TOP w0.102: BGA.P1 v1(13.12,16.32)
  BOTTOM w0.102: 5.21,16.99 13.34,16.99 13.53,16.79 13.53,16.53 13.33,16.32 v1(13.12,16.32)
PL22B: length 11.3
  TOP w0.102: BGA.M4 v1(15.52,17.92)
  BOTTOM w0.102: 5.21,17.16 13.41,17.16 13.57,17.01 14.04,17.01 14.55,17.52 15.12,17.52 v1(15.52,17.92)
PL23A: length 8.6
  TOP w0.102: BGA.R1 v1(13.12,15.52)
  L3_SIGNAL w0.102: v1(13.12,15.52) 12.79,15.52 12.57,15.74 5.21,15.74
PL23B: length 10.2
  TOP w0.102: BGA.P3 v1(14.72,16.32)
  L3_SIGNAL w0.102: 5.21,15.92 14.32,15.92 v1(14.72,16.32)
PL23C: length 9.5
  TOP w0.102: BGA.P2 v1(13.92,16.32)
  L3_SIGNAL w0.102: 5.21,16.75 13.49,16.75 v1(13.92,16.32)
PL23D: length 14.3
  TOP w0.102: BGA.M6 v1(17.12,18.72)
  L3_SIGNAL w0.102: 5.21,16.92 13.57,16.92 13.77,16.72 16.72,16.72 17.12,17.12 v1(17.12,18.72)
PL24A: length 12.3
  TOP w0.102: BGA.N4 v1(15.52,17.12)
  BOTTOM w0.102: 14.84,5.62 14.84,14 15.12,14.28 15.12,16.49 15.13,16.5 15.13,16.52 15.52,16.9 v1(15.52,17.12)
PL24B: length 10.8
  TOP w0.102: BGA.T1 v1(13.12,14.72)
  BOTTOM w0.102: 14.67,5.62 14.67,14 14.35,14.32 13.52,14.32 v1(13.12,14.72)
PL24C: length 9.6
  TOP w0.102: BGA.R2 v1(13.92,15.52)
  L3_SIGNAL w0.102: v1(13.92,15.52) 13.52,15.12 12.77,15.12 12.43,14.79 5.21,14.79
PL24D: length 8.8
  TOP w0.102: BGA.U1 v1(13.12,13.92)
  L3_SIGNAL w0.102: v1(13.12,13.92) 12.43,14.61 5.21,14.61
PL25A: length 9.8
  TOP w0.102: BGA.T2 v1(13.92,14.72)
  L4_SIGNAL w0.102: 14.33,5.61 14.33,14.2 14.14,14.39 14.14,14.5 v1(13.92,14.72)
PL25B: length 13.4
  TOP w0.102: BGA.N5 v1(16.32,17.12)
  L4_SIGNAL w0.102: v1(16.32,17.12) 15.92,16.72 15.92,16.15 15.69,15.92 15.35,15.92 15.12,15.69 15.12,15.28 14.96,15.12 14.55,15.12 14.32,14.89 14.32,14.46 14.51,14.27 14.51,5.61
PL25C: length 11.2
  TOP w0.102: BGA.P4 v1(15.52,16.32)
  L4_SIGNAL w0.102: 5.16,16.4 12.53,16.4 12.84,16.72 15.12,16.72 v1(15.52,16.32)
PL25D: length 10.4
  TOP w0.102: BGA.R3 v1(14.72,15.52)
  L4_SIGNAL w0.102: 5.16,16.23 12.53,16.23 12.84,15.92 14.32,15.92 v1(14.72,15.52)
PR2A: length 8.9
  TOP w0.102: BGA.B18 27.5,26.32 27.72,26.1 35.97,26.1
PR2B: length 9.8
  TOP w0.102: 35.97,25.92 26.72,25.92 BGA.C17
PR2C: length 13.6
  TOP w0.102: BGA.F14 v1(24.32,22.72)
  BOTTOM w0.102: 25.03,35.5 25.03,25.82 24.72,25.51 24.72,23.35 24.32,22.95 v1(24.32,22.72)
PR2D: length 12.1
  TOP w0.102: BGA.D16 v1(25.12,24.32)
  BOTTOM w0.102: 25.21,35.5 25.21,25.82 25.54,25.5 25.54,24.73 25.12,24.32 v1(25.12,24.32)
PR3A: length 13
  TOP w0.102: BGA.E15 v1(24.32,23.52)
  L3_SIGNAL w0.102: v1(24.32,23.52) 24.55,23.52 24.95,23.92 25.34,23.92 25.52,24.1 25.52,24.54 25.7,24.72 35.96,24.72
PR3B: length 9.9
  TOP w0.102: BGA.C18 v1(26.72,25.12)
  L3_SIGNAL w0.102: v1(26.72,25.12) 27.04,25.12 27.26,24.9 35.96,24.9
PR3C: length 14.4
  TOP w0.102: BGA.G13 v1(23.52,21.92)
  BOTTOM w0.102: v1(23.52,21.92) 23.92,22.32 24.15,22.32 24.15,22.32 24.49,22.32 24.72,22.55 24.72,22.89 24.95,23.12 25.36,23.12 25.52,23.28 25.52,23.69 25.75,23.92 26.16,23.92 26.48,24.24 35.98,24.24
PR3D: length 13.7
  TOP w0.102: BGA.G14 v1(24.32,21.92)
  BOTTOM w0.102: v1(24.32,21.92) 24.34,21.92 24.74,22.32 25.31,22.32 25.52,22.53 25.52,23.03 25.61,23.12 26.15,23.12 26.32,23.29 26.32,23.83 26.55,24.07 35.98,24.07
PR4A: length 11.7
  TOP w0.102: BGA.F15 v1(25.12,22.72)
  L3_SIGNAL w0.102: 35.96,23.44 27.26,23.44 26.93,23.12 25.52,23.12 v1(25.12,22.72)
PR4B: length 10.9
  TOP w0.102: BGA.D17 v1(25.92,24.32)
  L3_SIGNAL w0.102: v1(25.92,24.32) 26.28,23.96 26.93,23.96 27.26,23.62 35.96,23.62
PR4C: length 12.4
  TOP w0.102: BGA.E16 v1(25.12,23.52)
  L4_SIGNAL w0.102: 35.97,24.44 26.59,24.44 26.59,24.43 26.3,24.73 25.76,24.73 25.52,24.49 25.52,24.47 25.52,24.15 25.12,23.75 v1(25.12,23.52)
PR4D: length 15.3
  TOP w0.102: BGA.H13 v1(23.52,21.12)
  L4_SIGNAL w0.102: v1(23.52,21.12) 23.92,21.52 23.92,22.9 24.14,23.12 25.29,23.12 25.52,23.35 25.52,23.66 25.52,23.69 25.75,23.92 26.28,23.92 26.62,24.26 35.97,24.26
PR5A: length 11.7
  TOP w0.102: BGA.G15 v1(25.12,21.92)
  L4_SIGNAL w0.102: v1(25.12,21.92) 25.52,22.32 25.8,22.32 26.15,22.32 26.52,22.69 35.97,22.69
PR5B: length 10.9
  TOP w0.102: BGA.F16 v1(25.92,23.52)
  L4_SIGNAL w0.102: v1(25.92,23.52) 26.58,22.86 35.97,22.86
PR6C: length 9.8
  TOP w0.102: BGA.E17 26.72,24.32 35.97,24.32
PR6D: length 8.9
  TOP w0.102: 35.97,24.5 27.73,24.5 27.51,24.72 BGA.D18
PR7A: length 10.9
  TOP w0.102: BGA.G16 v1(25.92,21.92)
  L4_SIGNAL w0.102: v1(25.92,21.92) 26.15,21.92 26.57,22.34 27.04,22.34 27.33,22.05 35.97,22.05
PR7B: length 11.7
  TOP w0.102: BGA.H15 v1(25.12,21.12)
  L4_SIGNAL w0.102: v1(25.12,21.12) 25.52,21.52 26.95,21.52 27.3,21.87 35.97,21.87
PR7C: length 13.2
  TOP w0.102: BGA.H14 v1(24.32,21.12)
  L3_SIGNAL w0.102: v1(24.32,21.12) 24.32,21.35 24.72,21.75 24.72,22.1 24.94,22.32 26.86,22.32 27.31,22.77 35.96,22.77
PR7D: length 10.7
  TOP w0.102: BGA.F17 v1(25.92,22.72)
  L3_SIGNAL w0.102: v1(25.92,22.72) 27.01,22.72 27.24,22.94 35.96,22.94
PR8A: length 9.1
  TOP w0.102: 35.97,23.4 27.93,23.4 27.41,23.92 BGA.E18
PR8B: length 10
  TOP w0.102: 35.97,23.22 27.93,23.22 27.43,22.72 26.72,22.72 BGA.G17
PR8C: length 11.3
  TOP w0.102: BGA.H16 v1(25.92,21.12)
  BOTTOM w0.102: v1(25.92,21.12) 26.32,21.52 26.61,21.52 26.61,21.52 27,21.52 27.19,21.71 27.19,22.1 27.37,22.28 35.98,22.28
PR8D: length 10.5
  TOP w0.102: BGA.F18 v1(26.72,23.52)
  BOTTOM w0.102: v1(26.72,23.52) 26.72,23.1 27.36,22.46 35.98,22.46
PR9A: length 11.7
  TOP w0.102: BGA.J15 v1(25.12,20.32)
  L3_SIGNAL w0.102: 35.96,21.04 28.09,21.04 27.77,20.72 25.52,20.72 v1(25.12,20.32)
PR9B: length 10.1
  TOP w0.102: BGA.H17 v1(26.72,21.12)
  L3_SIGNAL w0.102: 35.96,21.22 28.1,21.22 27.78,21.53 27.34,21.53 26.93,21.12 v1(26.72,21.12)
PR10C: length 13.9
  TOP w0.102: BGA.J13 v1(23.52,20.32)
  L3_SIGNAL w0.102: 35.96,21.97 27.34,21.97 26.89,21.52 24.95,21.52 24.72,21.29 24.72,20.91 24.53,20.72 23.92,20.72 v1(23.52,20.32)
PR10D: length 9.9
  TOP w0.102: BGA.G18 v1(26.72,21.92)
  L3_SIGNAL w0.102: 35.96,22.15 27.26,22.15 27.03,21.92 v1(26.72,21.92)
PR11A: length 10.9
  TOP w0.102: BGA.J16 v1(25.92,20.32)
  L4_SIGNAL w0.102: 35.97,20.27 28.11,20.27 27.76,19.92 26.32,19.92 v1(25.92,20.32)
PR11B: length 10.1
  TOP w0.102: BGA.J17 v1(26.72,20.32)
  L4_SIGNAL w0.102: 35.97,20.45 28.12,20.45 27.84,20.72 27.33,20.72 26.93,20.32 v1(26.72,20.32)
PR11C: length 12.5
  TOP w0.102: BGA.J14 v1(24.32,20.32)
  BOTTOM w0.102: v1(24.32,20.32) 24.34,20.32 24.74,19.92 27.81,19.92 28.14,20.26 35.98,20.26
PR11D: length 14.1
  TOP w0.102: BGA.J12 v1(22.72,20.32)
  BOTTOM w0.102: v1(22.72,20.32) 23.12,20.72 27.87,20.72 28.15,20.43 35.98,20.43
PR12A: length 9.1
  TOP w0.102: BGA.H18 v1(27.52,21.12)
  L4_SIGNAL w0.102: v1(27.52,21.12) 27.89,21.12 28.12,21.34 35.97,21.34
PR12B: length 12.8
  TOP w0.102: BGA.K15 v1(25.12,19.52)
  L4_SIGNAL w0.102: 35.97,21.52 27.35,21.52 27.12,21.29 27.12,20.91 26.93,20.72 25.71,20.72 25.52,20.53 25.52,19.92 v1(25.12,19.52)
PR15A: length 12.4
  TOP w0.102: BGA.K14 v1(24.32,19.52)
  L3_SIGNAL w0.102: v1(24.32,19.52) 24.72,19.92 35.96,19.92
PR15B: length 9.1
  TOP w0.102: BGA.J18 v1(27.52,20.32)
  L3_SIGNAL w0.102: 35.96,20.1 28.04,20.1 27.82,20.32 v1(27.52,20.32)
PR16A: length 10.9
  TOP w0.102: BGA.K16 v1(25.92,19.52)
  L4_SIGNAL w0.102: 35.97,18.85 27.29,18.85 27.02,19.12 26.55,19.12 26.15,19.52 v1(25.92,19.52)
PR16B: length 10
  TOP w0.102: BGA.K17 v1(26.72,19.52)
  L4_SIGNAL w0.102: 35.97,19.03 27.37,19.03 26.88,19.52 v1(26.72,19.52)
PR16C: length 15.5
  TOP w0.102: BGA.K12 v1(21.92,19.52)
  BOTTOM w0.102: 35.98,18.66 27.38,18.66 27.04,18.32 24.09,18.32 23.92,18.49 23.92,18.94 23.74,19.12 22.32,19.12 v1(21.92,19.52)
PR16D: length 13.3
  TOP w0.102: BGA.K13 v1(23.52,19.52)
  BOTTOM w0.102: 35.98,18.84 27.39,18.84 27.1,19.12 24,19.12 23.6,19.52 v1(23.52,19.52)
PR17A: length 9.1
  TOP w0.102: BGA.K18 v1(27.52,19.52)
  L3_SIGNAL w0.102: v1(27.52,19.52) 27.84,19.52 28.06,19.3 35.96,19.3
PR17B: length 10.8
  TOP w0.102: BGA.L16 v1(25.92,18.72)
  L3_SIGNAL w0.102: 35.96,19.12 27.94,19.12 27.94,19.12 26.32,19.12 v1(25.92,18.72)
PR17C: length 12.2
  TOP w0.102: BGA.L15 v1(25.12,18.72)
  L4_SIGNAL w0.102: v1(25.12,18.72) 25.52,19.12 26.09,19.12 26.09,19.12 26.32,18.89 26.32,18.89 26.32,18.46 26.49,18.29 35.97,18.29
PR17D: length 13.3
  TOP w0.102: BGA.L13 v1(23.52,18.72)
  L4_SIGNAL w0.102: 35.97,18.11 26.42,18.11 26.21,18.32 23.92,18.32 v1(23.52,18.72)
PR18A: length 10.6
  TOP w0.102: BGA.L17 v1(26.72,18.72)
  L3_SIGNAL w0.102: 35.96,18.22 26.55,18.22 26.45,18.31 26.45,18.45 v1(26.72,18.72)
PR18B: length 10.8
  TOP w0.102: BGA.M16 v1(25.92,17.92)
  L3_SIGNAL w0.102: v1(25.92,17.92) 26.19,18.19 26.33,18.19 26.48,18.04 35.96,18.04
PR19C: length 9
  TOP w0.102: 35.99,18.81 27.43,18.81 BGA.L18
PR19D: length 9
  TOP w0.102: 35.99,18.63 27.43,18.63 BGA.M18
PR21A: length 9.8
  TOP w0.102: 35.99,17.91 26.73,17.91 BGA.M17
PR21B: length 9
  TOP w0.102: BGA.N18 27.28,17.52 27.5,17.73 35.99,17.73
PR21C: length 13.1
  TOP w0.102: BGA.L14 v1(24.32,18.72)
  L3_SIGNAL w0.102: v1(24.32,18.72) 24.72,18.32 24.72,17.75 24.95,17.52 26.87,17.52 27.05,17.7 35.96,17.7
PR21D: length 10
  TOP w0.102: BGA.N17 v1(26.72,17.12)
  L3_SIGNAL w0.102: v1(26.72,17.12) 27.12,17.52 35.96,17.52
PR22A: length 11.7
  TOP w0.102: BGA.M15 v1(25.12,17.92)
  L4_SIGNAL w0.102: v1(25.12,17.92) 25.52,17.52 27.78,17.52 28,17.3 35.97,17.3
PR22B: length 9
  TOP w0.102: BGA.P18 v1(27.52,17.12)
  L4_SIGNAL w0.102: 35.97,17.12 v1(27.52,17.12)
PR22C: length 12.5
  TOP w0.102: BGA.M14 v1(24.32,17.92)
  BOTTOM w0.102: 35.98,17.24 28.12,17.24 27.84,17.52 24.72,17.52 v1(24.32,17.92)
PR22D: length 10.9
  TOP w0.102: BGA.N16 v1(25.92,17.12)
  BOTTOM w0.102: v1(25.92,17.12) 26.32,16.72 27.79,16.72 28.13,17.06 35.98,17.06
PR23A: length 10.9
  TOP w0.102: BGA.P17 v1(25.92,16.32)
  L4_SIGNAL w0.102: 35.97,16.25 27.37,16.25 27.03,15.92 26.32,15.92 v1(25.92,16.32)
PR23B: length 11.7
  TOP w0.102: BGA.N15 v1(25.12,17.12)
  L4_SIGNAL w0.102: 35.97,16.43 27.37,16.43 27.08,16.72 25.52,16.72 v1(25.12,17.12)
PR23C: length 9.9
  TOP w0.102: BGA.R18 v1(26.72,16.32)
  L3_SIGNAL w0.102: 35.96,16.54 27.32,16.54 27.1,16.32 v1(26.72,16.32)
PR23D: length 14
  TOP w0.102: BGA.M13 v1(23.52,17.92)
  L3_SIGNAL w0.102: v1(23.52,17.92) 23.52,17.15 23.95,16.72 35.96,16.72
PR24A: length 11.6
  TOP w0.102: BGA.P16 v1(25.12,16.32)
  L3_SIGNAL w0.102: 35.96,15.92 26.09,15.92 25.52,15.92 v1(25.12,16.32)
PR24B: length 9.9
  TOP w0.102: BGA.T18 v1(26.72,15.52)
  L3_SIGNAL w0.102: v1(26.72,15.52) 27.06,15.52 27.28,15.74 35.96,15.74
PR24C: length 10.8
  TOP w0.102: BGA.R17 v1(25.92,15.52)
  BOTTOM w0.102: v1(25.92,15.52) 25.52,15.12 25.52,14.41 25.21,14.1 25.21,5.62
PR24D: length 12.4
  TOP w0.102: BGA.N14 v1(24.32,17.12)
  BOTTOM w0.102: 25.03,5.62 25.03,14.09 24.72,14.4 24.72,16.72 v1(24.32,17.12)
PR25A: length 11.9
  TOP w0.102: BGA.P15 v1(24.32,16.32)
  L4_SIGNAL w0.102: v1(24.32,16.32) 24.72,15.92 24.72,14.49 24.97,14.24 25.28,14.24 25.44,14.07 25.44,5.61
PR25B: length 10.4
  TOP w0.102: BGA.U18 v1(26.72,14.72)
  L4_SIGNAL w0.102: 25.62,5.61 25.62,14.05 25.81,14.24 26.24,14.24 v1(26.72,14.72)
PR25C: length 10.6
  TOP w0.102: BGA.R16 v1(25.12,15.52)
  L3_SIGNAL w0.102: v1(25.12,15.52) 25.52,15.12 25.52,5.61
PR25D: length 9.8
  TOP w0.102: BGA.T17 v1(25.92,14.72)
  L3_SIGNAL w0.102: v1(25.92,14.72) 25.92,14.42 25.7,14.2 25.7,5.61
PT9A: length 8.4
  TOP w0.102: 14.54,35.47 14.54,27.69 14.32,27.47 BGA.A2
PT9B: length 9.3
  TOP w0.102: BGA.B3 14.72,26.72 14.72,35.47
PT9C: length 12
  TOP w0.102: BGA.D4 v1(15.52,24.32)
  BOTTOM w0.102: 16.23,35.5 16.23,26.55 15.92,26.24 BGA.D4 v1(15.52,24.32)
PT9D: length 12.8
  TOP w0.102: BGA.E5 v1(16.32,23.52)
  BOTTOM w0.102: v1(16.32,23.52) BGA.E5 16.72,26.24 16.41,26.55 16.41,35.5
PT10A: length 11.2
  TOP w0.102: BGA.C3 v1(14.72,25.12)
  L3_SIGNAL w0.102: v1(14.72,25.12) 14.93,25.12 15.03,25.22 15.03,25.52 15.19,25.68 15.19,35.47
PT10B: length 11.2
  TOP w0.102: BGA.C4 v1(15.52,25.12)
  L3_SIGNAL w0.102: 15.37,35.47 15.37,25.61 15.21,25.45 15.21,25.22 15.31,25.12 v1(15.52,25.12)
PT10C: length 13.3
  TOP w0.102: BGA.F7 v1(18.72,23.52)
  L4_SIGNAL w0.102: v1(18.72,23.52) 18.32,23.92 18.32,24.49 18.09,24.72 17.75,24.72 17.52,24.95 17.52,26.22 17.21,26.53 17.21,35.44
PT10D: length 12
  TOP w0.102: BGA.E6 v1(17.12,24.32)
  L4_SIGNAL w0.102: 17.03,35.44 17.03,26.54 16.72,26.23 16.72,24.73 17.12,24.33 v1(17.12,24.32)
PT11A: length 8.4
  TOP w0.102: 15.34,35.47 15.34,27.65 15.12,27.43 BGA.A3
PT11B: length 9.3
  TOP w0.102: 15.52,35.47 15.52,26.72 BGA.B4
PT11C: length 11.8
  TOP w0.102: BGA.D5 v1(16.32,24.32)
  L4_SIGNAL w0.102: 15.92,35.44 15.92,24.72 v1(16.32,24.32)
PT11D: length 10.2
  TOP w0.102: BGA.B5 v1(16.32,25.92)
  L4_SIGNAL w0.102: 16.1,35.44 16.1,26.44 16.32,26.22 v1(16.32,25.92)
PT12A: length 8.5
  TOP w0.102: BGA.A4 16.23,27.43 16.23,35.47
PT12B: length 8.5
  TOP w0.102: 16.41,35.47 16.41,27.43 BGA.A5
PT13A: length 11.2
  TOP w0.102: BGA.C5 v1(16.32,25.12)
  L3_SIGNAL w0.102: 16.23,35.47 16.23,26.5 15.92,26.19 15.92,26.09 15.92,25.51 16.31,25.12 v1(16.32,25.12)
PT13B: length 11.2
  TOP w0.102: BGA.D6 v1(17.12,25.12)
  L3_SIGNAL w0.102: v1(17.12,25.12) 16.72,25.52 16.72,26.19 16.41,26.51 16.41,35.47
PT14A: length 9.3
  TOP w0.102: BGA.B6 17.12,26.72 17.12,35.47
PT14B: length 8.4
  TOP w0.102: 17.3,35.47 17.3,27.69 17.52,27.47 BGA.A6
PT14C: length 11.1
  TOP w0.102: BGA.D7 v1(17.92,25.12)
  L3_SIGNAL w0.102: v1(17.92,25.12) 17.52,25.52 17.52,35.47
PT14D: length 10.2
  TOP w0.102: BGA.C6 v1(17.12,25.92)
  L3_SIGNAL w0.102: v1(17.12,25.92) 17.12,26.21 17.34,26.43 17.34,35.47
PT15A: length 8.4
  TOP w0.102: 18.1,35.47 18.1,27.69 18.32,27.47 BGA.A7
PT15B: length 9.3
  TOP w0.102: BGA.B7 17.92,26.72 17.92,35.47
PT16A: length 11.2
  TOP w0.102: BGA.D8 v1(18.72,25.12)
  BOTTOM w0.102: v1(18.72,25.12) 18.72,25.13 18.32,25.53 18.32,26.19 18.02,26.49 18.02,35.5
PT16B: length 12
  TOP w0.102: BGA.E7 v1(17.92,24.32)
  BOTTOM w0.102: 17.84,35.5 17.84,26.48 17.52,26.16 17.52,24.72 v1(17.92,24.32)
PT17A: length 9.3
  TOP w0.102: 18.72,35.47 18.72,26.72 BGA.B8
PT17B: length 8.4
  TOP w0.102: BGA.A8 19.12,27.47 18.9,27.69 18.9,35.47
PT17C: length 10.4
  TOP w0.102: BGA.C7 v1(17.92,25.92)
  L3_SIGNAL w0.102: 18.23,35.47 18.23,26.02 18.13,25.92 v1(17.92,25.92)
PT17D: length 10.4
  TOP w0.102: BGA.C8 v1(18.72,25.92)
  L3_SIGNAL w0.102: 18.41,35.47 18.41,26.02 18.51,25.92 v1(18.72,25.92)
PT18A: length 8.4
  TOP w0.102: 19.7,35.47 19.7,27.69 19.92,27.47 BGA.A9
PT18B: length 9.3
  TOP w0.102: BGA.B9 19.52,26.72 19.52,35.47
PT18C: length 12
  TOP w0.102: BGA.E8 v1(18.72,24.32)
  L4_SIGNAL w0.102: 18.63,35.44 18.63,26.42 18.32,26.11 18.32,25.94 18.32,24.95 18.72,24.55 v1(18.72,24.32)
PT18D: length 12.8
  TOP w0.102: BGA.F8 v1(19.52,23.52)
  L4_SIGNAL w0.102: v1(19.52,23.52) 19.52,23.52 19.12,23.92 19.12,26.11 18.81,26.42 18.81,35.44
PT21A: length 8.4
  TOP w0.102: 20.5,35.47 20.5,27.69 20.72,27.47 BGA.A10
PT21B: length 9.3
  TOP w0.102: BGA.B10 20.32,26.72 20.32,35.47
PT21C: length 10.2
  TOP w0.102: BGA.C9 v1(19.52,25.92)
  L3_SIGNAL w0.102: 19.3,35.47 19.3,26.43 19.52,26.21 v1(19.52,25.92)
PT21D: length 11.1
  TOP w0.102: BGA.D9 v1(19.52,25.12)
  L3_SIGNAL w0.102: 19.12,35.47 19.12,25.52 v1(19.52,25.12)
PT22A: length 10.4
  TOP w0.102: BGA.C10 v1(20.32,25.92)
  BOTTOM w0.102: v1(20.32,25.92) 20.53,25.92 20.63,26.02 20.63,35.5
PT22B: length 10.4
  TOP w0.102: BGA.B11 v1(21.12,25.92)
  BOTTOM w0.102: 20.81,35.5 20.81,26.02 20.91,25.92 v1(21.12,25.92)
PT22C: length 12
  TOP w0.102: BGA.E9 v1(19.52,24.32)
  BOTTOM w0.102: 19.43,35.5 19.43,26.44 19.12,26.14 19.12,24.72 v1(19.52,24.32)
PT22D: length 11.2
  TOP w0.102: BGA.D10 v1(20.32,25.12)
  BOTTOM w0.102: 19.61,35.5 19.61,26.44 19.92,26.13 19.92,25.52 v1(20.32,25.12)
PT25A: length 9.4
  TOP w0.102: BGA.B12 v1(21.92,26.72)
  L3_SIGNAL w0.102: 21.7,35.47 21.7,27.23 21.92,27.01 v1(21.92,26.72)
PT25B: length 11.1
  TOP w0.102: BGA.C11 v1(21.12,25.12)
  L3_SIGNAL w0.102: v1(21.12,25.12) BGA.C11 21.52,35.47
PT25C: length 13.5
  TOP w0.102: BGA.F9 v1(19.52,22.72)
  L4_SIGNAL w0.102: v1(19.52,22.72) BGA.F9 19.92,26.32 20.12,26.52 20.12,35.44
PT25D: length 12.8
  TOP w0.102: BGA.F10 v1(20.32,23.52)
  L4_SIGNAL w0.102: 20.3,35.44 20.3,26.55 20.72,26.13 20.72,23.92 v1(20.32,23.52)
PT26A: length 8.5
  TOP w0.102: 21.83,35.47 21.83,27.43 21.52,27.12 BGA.A11
PT26B: length 8.5
  TOP w0.102: 22.01,35.47 22.01,27.43 BGA.A12
PT26C: length 12
  TOP w0.102: BGA.E10 v1(20.32,24.32)
  L3_SIGNAL w0.102: 20.21,35.47 20.21,26.44 19.92,26.15 19.92,24.72 v1(20.32,24.32)
PT26D: length 12.8
  TOP w0.102: BGA.E11 v1(21.12,23.52)
  L3_SIGNAL w0.102: v1(21.12,23.52) 21.12,23.53 20.72,23.93 20.72,26.13 20.39,26.46 20.39,35.47
PT27A: length 10.5
  TOP w0.102: BGA.C12 v1(21.92,25.92)
  L3_SIGNAL w0.102: 22.43,35.47 22.43,26.52 22.23,26.32 22.23,26.02 22.13,25.92 v1(21.92,25.92)
PT27B: length 10.5
  TOP w0.102: BGA.B13 v1(22.72,25.92)
  L3_SIGNAL w0.102: 22.61,35.47 22.61,26.45 22.41,26.25 22.41,26.02 22.51,25.92 v1(22.72,25.92)
PT27C: length 12
  TOP w0.102: BGA.D11 v1(21.12,24.32)
  BOTTOM w0.102: v1(21.12,24.32) 21.12,24.5 21.52,24.9 21.52,26.96 21.84,27.27 21.84,35.5
PT27D: length 11.2
  TOP w0.102: BGA.D12 v1(21.92,25.12)
  BOTTOM w0.102: 22.02,35.5 22.02,27.3 22.32,26.99 22.32,25.52 v1(21.92,25.12)
PT28A: length 8.5
  TOP w0.102: BGA.A13 23.43,27.43 23.43,35.47
PT28B: length 8.5
  TOP w0.102: BGA.A14 23.61,27.43 23.61,35.47
PT32A: length 15.8
  TOP w0.102: BGA.F11 v1(21.12,22.72)
  BOTTOM w0.102: v1(21.12,22.72) BGA.F11 21.52,24.49 21.75,24.72 21.85,24.72 23.72,24.72 23.92,24.92 23.92,26.13 23.61,26.44 23.61,35.5
PT32B: length 11.2
  TOP w0.102: BGA.C13 v1(22.72,25.12)
  BOTTOM w0.102: v1(22.72,25.12) BGA.C13 23.12,26.12 23.43,26.43 23.43,35.5
PT33A: length 10.4
  TOP w0.102: BGA.B14 v1(23.52,25.92)
  L3_SIGNAL w0.102: v1(23.52,25.92) 23.73,25.92 23.83,26.02 23.83,35.47
PT33B: length 10.4
  TOP w0.102: BGA.B15 v1(24.32,25.92)
  L3_SIGNAL w0.102: v1(24.32,25.92) 24.11,25.92 24.01,26.02 24.01,35.47
PT33C: length 12
  TOP w0.102: BGA.E12 v1(21.92,24.32)
  L4_SIGNAL w0.102: 21.82,35.44 21.82,27.29 21.52,26.99 21.52,24.72 v1(21.92,24.32)
PT33D: length 12.8
  TOP w0.102: BGA.F12 v1(21.92,23.52)
  L4_SIGNAL w0.102: 22,35.44 22,27.29 22.32,26.97 22.32,23.92 v1(21.92,23.52)
PT34A: length 11.2
  TOP w0.102: BGA.C14 v1(23.52,25.12)
  L4_SIGNAL w0.102: v1(23.52,25.12) 23.12,25.52 23.12,26.19 23.41,26.48 23.41,35.44
PT34B: length 11.2
  TOP w0.102: BGA.C15 v1(24.32,25.12)
  L4_SIGNAL w0.102: 23.59,35.44 23.59,26.5 23.92,26.16 23.92,25.52 v1(24.32,25.12)
PT34C: length 13.5
  TOP w0.102: BGA.D13 v1(22.72,24.32)
  L4_SIGNAL w0.102: v1(22.72,24.32) BGA.D13 24.39,24.72 24.6,24.72 24.72,24.84 24.72,25.49 25.03,25.81 25.03,35.44
PT34D: length 14.8
  TOP w0.102: BGA.E13 v1(22.72,23.52)
  L4_SIGNAL w0.102: 25.21,35.44 25.21,25.8 25.53,25.48 25.53,24.96 25.29,24.72 24.85,24.72 24.72,24.59 24.72,24.14 24.5,23.92 BGA.E13 v1(22.72,23.52)
